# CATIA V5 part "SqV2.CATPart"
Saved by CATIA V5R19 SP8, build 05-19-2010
Part number: SqV2
Publications: "Droite.1", "Plan.1"
Bounding box of the stored display mesh (mm): x -30 to 160, y 0 to 0, z 0 to 20
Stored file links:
  F:\Travail\2e année\IAO\Projetsave\SqV2.CATPart
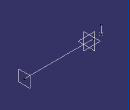
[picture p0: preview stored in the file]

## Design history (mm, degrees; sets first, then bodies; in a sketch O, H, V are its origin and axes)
Set1
  Plane1: type Offset, RefPlane yz-plane, Offset 160
  Point1: (-30, 0, 0)
  Line1: type PtDir, RefPoint Point1, Direction xy-plane, Start 0, End 20
  Line2: type Normal, LineFirstUpto Plane1, RefPoint Point1, RefSkin yz-plane, Start 0, End 20
Body1 (main body)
